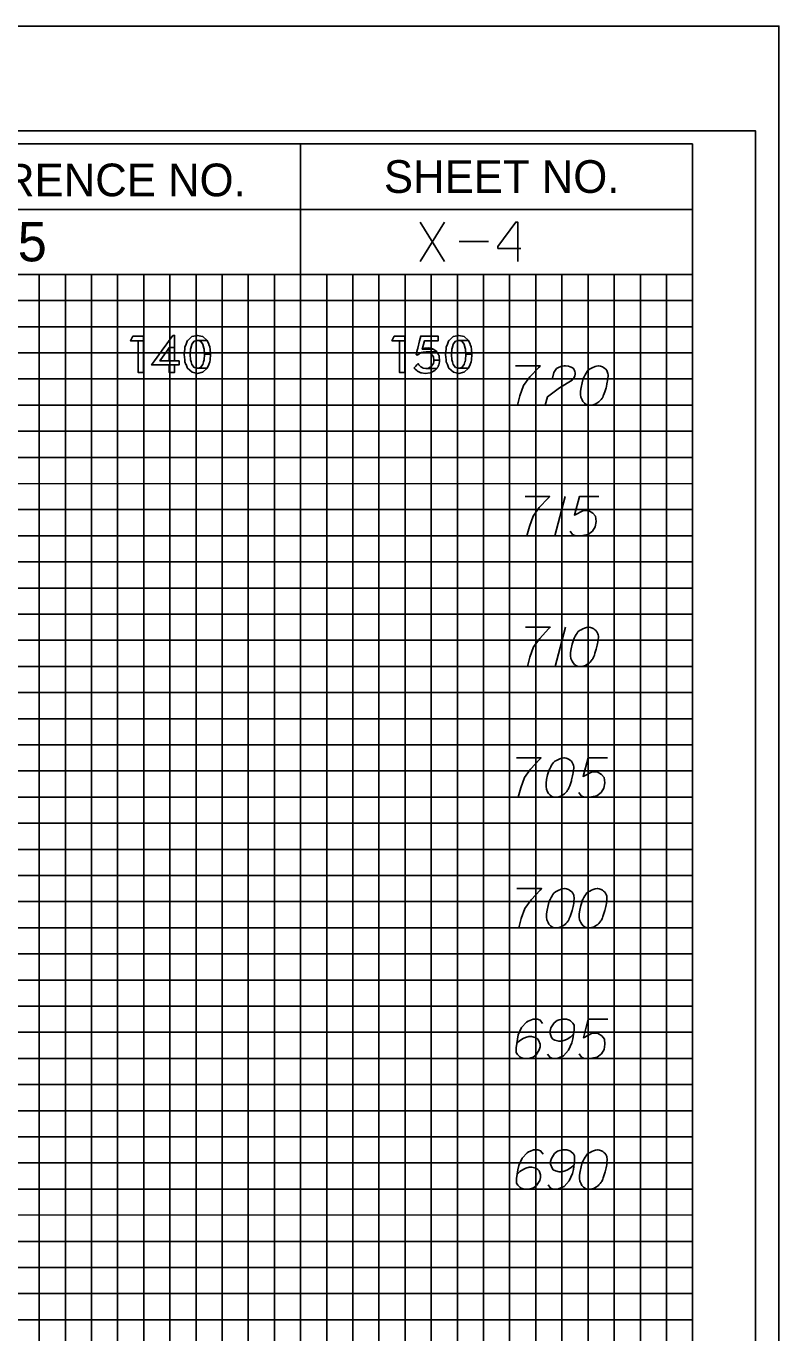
# Model space of a CAD drawing. Extents: x -13 to 323, y -5 to 1431.
# Drawn here: x 294.5 to 323.3, y 604.5 to 654.5 of the extents above; entities that cross this region are included whole.
import ezdxf

# ---------------------------------------------------------------- set-up
doc = ezdxf.new("R2010")
doc.units = 0
for name, color, linetype in [('Prop XS Elevation Labels', 7, 'Continuous'), ('Prop XS Offset Labels', 7, 'Continuous'), ('Prop XS Project Number', 7, 'Continuous'), ('Prop XS Sheet Number', 7, 'Continuous'), ('Sheet Cross Section CELL', 7, 'Continuous'), ('Sheet Cross Section Grid Major CELL', 7, 'Continuous'), ('Sheet Cross Section Grid Middle CELL', 7, 'Continuous'), ('Sheet Cross Section Grid Minor 1 CELL', 7, 'Continuous'), ('Sheet Cross Section Grid Minor 2 CELL', 7, 'Continuous'), ('Sheet Cutting Line CELL', 7, 'Continuous'), ('Sheet DOT Grid CELL', 7, 'Continuous'), ('Sheet Plot Border Inside CELL', 7, 'Continuous'), ('Sheet Plot Border Outside CELL', 7, 'Continuous')]:
    doc.layers.add(name, color=color, linetype=linetype)

msp = doc.modelspace()

# ---------------------------------------------------------------- linework, layer by layer
at = {"layer": 'Prop XS Elevation Labels'}
for p, q in [((315.124, 636.5), (314.723, 635)), ((315.142, 631.5), (314.74, 630))]:
    msp.add_line(p, q, dxfattribs=at)
for points in [[(313.228, 641.5), (314.173, 641.5), (314.114, 641.441), (313.772, 641.075), (313.535, 640.744), (313.394, 640.354), (313.299, 640)], [(314.634, 641.028), (314.693, 641.252), (314.787, 641.394), (314.894, 641.453), (315, 641.488), (315.083, 641.5), (315.142, 641.5), (315.248, 641.488), (315.319, 641.465), (315.354, 641.453), (315.425, 641.417), (315.461, 641.37), (315.484, 641.323), (315.496, 641.287), (315.508, 641.24), (315.508, 641.181), (315.496, 641.122), (315.484, 641.087), (315.461, 641.039), (315.425, 640.992), (315.39, 640.957), (314.906, 640.661), (314.445, 640.319), (314.362, 640), (315.437, 640)], [(316.417, 641.5), (316.394, 641.5), (316.323, 641.488), (316.276, 641.476), (316.24, 641.465), (316.181, 641.441), (316.11, 641.406), (316.051, 641.37), (315.992, 641.323), (315.957, 641.276), (315.921, 641.217), (315.886, 641.158), (315.85, 641.087), (315.827, 641.039), (315.803, 640.969), (315.768, 640.85), (315.732, 640.673), (315.709, 640.531), (315.709, 640.402), (315.721, 640.307), (315.768, 640.201), (315.803, 640.142), (315.862, 640.071), (315.933, 640.024), (315.968, 640.012), (316.039, 640), (316.098, 640), (316.193, 640.012), (316.276, 640.035), (316.335, 640.071), (316.417, 640.13), (316.453, 640.165), (316.5, 640.213), (316.535, 640.26), (316.559, 640.295), (316.583, 640.354), (316.594, 640.378), (316.618, 640.437), (316.642, 640.508), (316.665, 640.579), (316.677, 640.626), (316.689, 640.661), (316.701, 640.709), (316.724, 640.815), (316.736, 640.874), (316.748, 640.933), (316.76, 641.016), (316.772, 641.122), (316.772, 641.158), (316.76, 641.205), (316.748, 641.252), (316.713, 641.323), (316.677, 641.37), (316.642, 641.406), (316.594, 641.441), (316.547, 641.465), (316.512, 641.476), (316.476, 641.488), (316.417, 641.5)], [(313.589, 636.5), (314.533, 636.5), (314.474, 636.441), (314.132, 636.075), (313.896, 635.744), (313.754, 635.354), (313.659, 635)], [(316.411, 636.5), (315.667, 636.5), (315.478, 635.791), (315.821, 635.969), (316.022, 635.969), (316.187, 635.862), (316.282, 635.744), (316.305, 635.543), (316.27, 635.342), (316.175, 635.177), (316.01, 635.047), (315.726, 635), (315.514, 635), (315.408, 635.047), (315.313, 635.177)], [(313.606, 631.5), (314.551, 631.5), (314.492, 631.441), (314.149, 631.075), (313.913, 630.744), (313.772, 630.354), (313.677, 630)], [(316.039, 631.5), (316.016, 631.5), (315.945, 631.488), (315.898, 631.476), (315.862, 631.465), (315.803, 631.441), (315.732, 631.406), (315.673, 631.37), (315.614, 631.323), (315.579, 631.276), (315.543, 631.217), (315.508, 631.158), (315.472, 631.087), (315.449, 631.039), (315.425, 630.969), (315.39, 630.85), (315.354, 630.673), (315.331, 630.531), (315.331, 630.402), (315.343, 630.307), (315.39, 630.201), (315.425, 630.142), (315.484, 630.071), (315.555, 630.024), (315.591, 630.012), (315.661, 630), (315.72, 630), (315.815, 630.012), (315.898, 630.035), (315.957, 630.071), (316.039, 630.13), (316.075, 630.165), (316.122, 630.213), (316.157, 630.26), (316.181, 630.295), (316.205, 630.354), (316.217, 630.378), (316.24, 630.437), (316.264, 630.508), (316.287, 630.579), (316.299, 630.626), (316.311, 630.661), (316.323, 630.709), (316.347, 630.815), (316.358, 630.874), (316.37, 630.933), (316.382, 631.016), (316.394, 631.122), (316.394, 631.158), (316.382, 631.205), (316.37, 631.252), (316.335, 631.323), (316.299, 631.37), (316.264, 631.406), (316.217, 631.441), (316.169, 631.465), (316.134, 631.476), (316.098, 631.488), (316.039, 631.5)], [(313.258, 626.5), (314.203, 626.5), (314.144, 626.441), (313.801, 626.075), (313.565, 625.744), (313.423, 625.354), (313.329, 625)], [(315.1, 626.5), (315.077, 626.5), (315.006, 626.488), (314.959, 626.476), (314.923, 626.465), (314.864, 626.441), (314.793, 626.406), (314.734, 626.37), (314.675, 626.323), (314.64, 626.276), (314.604, 626.217), (314.569, 626.158), (314.534, 626.087), (314.51, 626.039), (314.486, 625.969), (314.451, 625.85), (314.415, 625.673), (314.392, 625.531), (314.392, 625.402), (314.404, 625.307), (314.451, 625.201), (314.486, 625.142), (314.545, 625.071), (314.616, 625.024), (314.652, 625.012), (314.723, 625), (314.781, 625), (314.876, 625.012), (314.959, 625.035), (315.018, 625.071), (315.1, 625.13), (315.136, 625.165), (315.183, 625.213), (315.219, 625.26), (315.242, 625.295), (315.266, 625.354), (315.278, 625.378), (315.301, 625.437), (315.325, 625.508), (315.349, 625.579), (315.36, 625.626), (315.372, 625.661), (315.384, 625.709), (315.408, 625.815), (315.419, 625.874), (315.431, 625.933), (315.443, 626.016), (315.455, 626.122), (315.455, 626.158), (315.443, 626.205), (315.431, 626.252), (315.396, 626.323), (315.36, 626.37), (315.325, 626.406), (315.278, 626.441), (315.23, 626.465), (315.195, 626.476), (315.16, 626.488), (315.1, 626.5)], [(316.742, 626.5), (315.998, 626.5), (315.809, 625.791), (316.152, 625.969), (316.352, 625.969), (316.518, 625.862), (316.612, 625.744), (316.636, 625.543), (316.6, 625.342), (316.506, 625.177), (316.341, 625.047), (316.057, 625), (315.845, 625), (315.738, 625.047), (315.644, 625.177)], [(313.276, 621.5), (314.22, 621.5), (314.161, 621.441), (313.819, 621.075), (313.583, 620.744), (313.441, 620.354), (313.346, 620)], [(315.118, 621.5), (315.094, 621.5), (315.024, 621.488), (314.977, 621.476), (314.941, 621.465), (314.882, 621.441), (314.811, 621.406), (314.752, 621.37), (314.693, 621.323), (314.658, 621.276), (314.622, 621.217), (314.587, 621.158), (314.551, 621.087), (314.528, 621.039), (314.504, 620.969), (314.469, 620.85), (314.433, 620.673), (314.409, 620.531), (314.409, 620.402), (314.421, 620.307), (314.469, 620.201), (314.504, 620.142), (314.563, 620.071), (314.634, 620.024), (314.669, 620.012), (314.74, 620), (314.799, 620), (314.894, 620.012), (314.977, 620.035), (315.036, 620.071), (315.118, 620.13), (315.154, 620.165), (315.201, 620.213), (315.236, 620.26), (315.26, 620.295), (315.283, 620.354), (315.295, 620.378), (315.319, 620.437), (315.342, 620.508), (315.366, 620.579), (315.378, 620.626), (315.39, 620.661), (315.402, 620.709), (315.425, 620.815), (315.437, 620.874), (315.449, 620.933), (315.461, 621.016), (315.473, 621.122), (315.473, 621.158), (315.461, 621.205), (315.449, 621.252), (315.413, 621.323), (315.378, 621.37), (315.342, 621.406), (315.295, 621.441), (315.248, 621.465), (315.213, 621.476), (315.177, 621.488), (315.118, 621.5)], [(316.37, 621.5), (316.346, 621.5), (316.276, 621.488), (316.228, 621.476), (316.193, 621.465), (316.134, 621.441), (316.063, 621.406), (316.004, 621.37), (315.945, 621.323), (315.909, 621.276), (315.874, 621.217), (315.838, 621.158), (315.803, 621.087), (315.779, 621.039), (315.756, 620.969), (315.721, 620.85), (315.685, 620.673), (315.661, 620.531), (315.661, 620.402), (315.673, 620.307), (315.721, 620.201), (315.756, 620.142), (315.815, 620.071), (315.886, 620.024), (315.921, 620.012), (315.992, 620), (316.051, 620), (316.146, 620.012), (316.228, 620.035), (316.287, 620.071), (316.37, 620.13), (316.406, 620.165), (316.453, 620.213), (316.488, 620.26), (316.512, 620.295), (316.535, 620.354), (316.547, 620.378), (316.571, 620.437), (316.594, 620.508), (316.618, 620.579), (316.63, 620.626), (316.642, 620.661), (316.653, 620.709), (316.677, 620.815), (316.689, 620.874), (316.701, 620.933), (316.713, 621.016), (316.724, 621.122), (316.724, 621.158), (316.713, 621.205), (316.701, 621.252), (316.665, 621.323), (316.63, 621.37), (316.594, 621.406), (316.547, 621.441), (316.5, 621.465), (316.464, 621.476), (316.429, 621.488), (316.37, 621.5)], [(314.262, 616.335), (314.168, 616.465), (314.061, 616.5), (313.896, 616.5), (313.778, 616.453), (313.707, 616.429), (313.648, 616.394), (313.459, 616.181), (313.329, 615.898), (313.294, 615.744), (313.246, 615.402), (313.246, 615.224), (313.294, 615.154), (313.388, 615.059), (313.423, 615.035), (313.542, 615), (313.695, 615), (313.813, 615.024), (313.896, 615.047), (314.014, 615.142), (314.132, 615.331), (314.168, 615.449), (314.168, 615.543), (314.109, 615.697), (314.061, 615.756), (313.979, 615.803), (313.837, 615.839), (313.73, 615.839), (313.601, 615.803), (313.518, 615.768), (313.376, 615.673), (313.305, 615.614), (313.27, 615.579)], [(314.451, 615.165), (314.545, 615.035), (314.652, 615), (314.817, 615), (314.935, 615.047), (315.006, 615.071), (315.065, 615.106), (315.254, 615.319), (315.384, 615.602), (315.419, 615.756), (315.467, 616.098), (315.467, 616.276), (315.419, 616.346), (315.325, 616.441), (315.289, 616.465), (315.171, 616.5), (315.018, 616.5), (314.9, 616.476), (314.817, 616.453), (314.699, 616.358), (314.581, 616.169), (314.545, 616.051), (314.545, 615.957), (314.604, 615.803), (314.652, 615.744), (314.734, 615.697), (314.876, 615.661), (314.982, 615.661), (315.112, 615.697), (315.195, 615.732), (315.337, 615.827), (315.408, 615.886), (315.443, 615.921)], [(316.754, 616.5), (316.01, 616.5), (315.821, 615.791), (316.163, 615.969), (316.364, 615.969), (316.529, 615.862), (316.624, 615.744), (316.647, 615.543), (316.612, 615.342), (316.517, 615.177), (316.352, 615.047), (316.069, 615), (315.856, 615), (315.75, 615.047), (315.655, 615.177)], [(314.28, 611.335), (314.185, 611.465), (314.079, 611.5), (313.914, 611.5), (313.795, 611.453), (313.725, 611.429), (313.666, 611.394), (313.477, 611.181), (313.347, 610.898), (313.311, 610.744), (313.264, 610.402), (313.264, 610.224), (313.311, 610.154), (313.406, 610.059), (313.441, 610.035), (313.559, 610), (313.713, 610), (313.831, 610.024), (313.914, 610.047), (314.032, 610.142), (314.15, 610.331), (314.185, 610.449), (314.185, 610.543), (314.126, 610.697), (314.079, 610.756), (313.996, 610.803), (313.854, 610.839), (313.748, 610.839), (313.618, 610.803), (313.536, 610.768), (313.394, 610.673), (313.323, 610.614), (313.288, 610.579)], [(314.468, 610.165), (314.563, 610.035), (314.669, 610), (314.835, 610), (314.953, 610.047), (315.024, 610.071), (315.083, 610.106), (315.272, 610.319), (315.401, 610.602), (315.437, 610.756), (315.484, 611.098), (315.484, 611.276), (315.437, 611.346), (315.342, 611.441), (315.307, 611.465), (315.189, 611.5), (315.036, 611.5), (314.917, 611.476), (314.835, 611.453), (314.717, 611.358), (314.598, 611.169), (314.563, 611.051), (314.563, 610.957), (314.622, 610.803), (314.669, 610.744), (314.752, 610.697), (314.894, 610.661), (315, 610.661), (315.13, 610.697), (315.213, 610.732), (315.354, 610.827), (315.425, 610.886), (315.461, 610.921)], [(316.382, 611.5), (316.358, 611.5), (316.287, 611.488), (316.24, 611.476), (316.204, 611.465), (316.145, 611.441), (316.074, 611.406), (316.015, 611.37), (315.956, 611.323), (315.921, 611.276), (315.885, 611.217), (315.85, 611.158), (315.815, 611.087), (315.791, 611.039), (315.767, 610.969), (315.732, 610.85), (315.697, 610.673), (315.673, 610.531), (315.673, 610.402), (315.685, 610.307), (315.732, 610.201), (315.767, 610.142), (315.827, 610.071), (315.897, 610.024), (315.933, 610.012), (316.004, 610), (316.063, 610), (316.157, 610.012), (316.24, 610.035), (316.299, 610.071), (316.382, 610.13), (316.417, 610.165), (316.464, 610.213), (316.5, 610.26), (316.523, 610.295), (316.547, 610.354), (316.559, 610.378), (316.582, 610.437), (316.606, 610.508), (316.63, 610.579), (316.642, 610.626), (316.653, 610.661), (316.665, 610.709), (316.689, 610.815), (316.701, 610.874), (316.712, 610.933), (316.724, 611.016), (316.736, 611.122), (316.736, 611.158), (316.724, 611.205), (316.712, 611.252), (316.677, 611.323), (316.642, 611.37), (316.606, 611.406), (316.559, 611.441), (316.512, 611.465), (316.476, 611.476), (316.441, 611.488), (316.382, 611.5)]]:
    msp.add_lwpolyline(points, dxfattribs=at)
at = {"layer": 'Prop XS Offset Labels'}
for points in [[(298.581, 642.641), (298.492, 642.459), (298.99, 642.459), (298.99, 642.641)], [(299.411, 641.693), (299.297, 641.534), (300.35, 641.534), (300.35, 641.693), (299.618, 641.693), (299.878, 642.059), (299.935, 642.139), (299.977, 642.199), (300.179, 642.199), (300.179, 642.668), (300.114, 642.668), (299.775, 642.199), (299.733, 642.139), (299.675, 642.059)], [(300.851, 641.255), (301.051, 641.214), (301.245, 641.255), (301.256, 641.257), (301.422, 641.409), (301.048, 641.409), (301.038, 641.411), (301.033, 641.413), (300.928, 641.442), (300.841, 641.555), (300.841, 641.556), (300.841, 641.556), (300.813, 641.657), (300.813, 641.659), (300.793, 641.732), (300.792, 641.736), (300.774, 641.939), (300.774, 641.941), (300.774, 641.943), (300.792, 642.145), (300.812, 642.222), (300.813, 642.224), (300.839, 642.322), (300.84, 642.325), (300.928, 642.44), (301.041, 642.469), (301.045, 642.47), (301.055, 642.473), (301.425, 642.473), (301.262, 642.622), (301.254, 642.624), (301.053, 642.668), (301.053, 642.668), (300.845, 642.624), (300.843, 642.622), (300.681, 642.473), (300.678, 642.47), (300.678, 642.469), (300.665, 642.44), (300.618, 642.325), (300.617, 642.322), (300.577, 642.224), (300.576, 642.222), (300.568, 642.145), (300.547, 641.943), (300.547, 641.941), (300.547, 641.939), (300.567, 641.736), (300.567, 641.732), (300.575, 641.659), (300.575, 641.657), (300.616, 641.556), (300.617, 641.555), (300.663, 641.442), (300.675, 641.413), (300.676, 641.411), (300.679, 641.409), (300.848, 641.257)], [(308.581, 642.641), (308.492, 642.459), (308.99, 642.459), (308.99, 642.641)], [(309.427, 641.94), (309.424, 641.928), (309.495, 641.928), (309.508, 641.94), (309.524, 641.954), (309.595, 641.997), (309.627, 642.007), (309.697, 642.029), (309.811, 642.035), (310.219, 642.035), (310.211, 642.05), (310.076, 642.145), (309.655, 642.145), (309.658, 642.158), (309.658, 642.158), (309.663, 642.178), (309.738, 642.456), (310.263, 642.456), (310.263, 642.641), (309.6, 642.641), (309.554, 642.456), (309.486, 642.178), (309.481, 642.158), (309.478, 642.145), (309.454, 642.05), (309.451, 642.035), (309.449, 642.029), (309.444, 642.007), (309.441, 641.997), (309.431, 641.954)], [(310.851, 641.255), (311.051, 641.214), (311.245, 641.255), (311.256, 641.257), (311.422, 641.409), (311.048, 641.409), (311.038, 641.411), (311.033, 641.413), (310.928, 641.442), (310.841, 641.555), (310.841, 641.556), (310.841, 641.556), (310.813, 641.657), (310.813, 641.659), (310.793, 641.732), (310.792, 641.736), (310.774, 641.939), (310.774, 641.941), (310.774, 641.943), (310.792, 642.145), (310.812, 642.222), (310.813, 642.224), (310.839, 642.322), (310.84, 642.325), (310.928, 642.44), (311.041, 642.469), (311.045, 642.47), (311.055, 642.473), (311.425, 642.473), (311.262, 642.622), (311.254, 642.624), (311.053, 642.668), (311.053, 642.668), (310.845, 642.624), (310.843, 642.622), (310.681, 642.473), (310.678, 642.47), (310.678, 642.469), (310.665, 642.44), (310.618, 642.325), (310.617, 642.322), (310.577, 642.224), (310.576, 642.222), (310.568, 642.145), (310.547, 641.943), (310.547, 641.941), (310.547, 641.939), (310.567, 641.736), (310.567, 641.732), (310.575, 641.659), (310.575, 641.657), (310.616, 641.556), (310.617, 641.555), (310.663, 641.442), (310.675, 641.413), (310.676, 641.411), (310.679, 641.409), (310.848, 641.257)], [(298.781, 642.459), (298.781, 641.25), (298.99, 641.25), (298.99, 642.459)], [(299.97, 642.059), (299.97, 641.693), (300.179, 641.693), (300.179, 642.059), (300.179, 642.139), (300.179, 642.199), (299.977, 642.199), (299.973, 642.139)], [(301.312, 642.145), (301.328, 641.943), (301.555, 641.943), (301.536, 642.145), (301.528, 642.222), (301.528, 642.224), (301.527, 642.224), (301.488, 642.322), (301.488, 642.322), (301.487, 642.325), (301.441, 642.44), (301.44, 642.44), (301.429, 642.469), (301.428, 642.47), (301.425, 642.473), (301.055, 642.473), (301.065, 642.47), (301.068, 642.469), (301.175, 642.44), (301.262, 642.325), (301.265, 642.322), (301.291, 642.224), (301.291, 642.222)], [(308.781, 642.459), (308.781, 641.25), (308.99, 641.25), (308.99, 642.459)], [(309.692, 642.158), (309.655, 642.145), (310.076, 642.145), (310.058, 642.158), (309.961, 642.178), (309.75, 642.178)], [(309.888, 642.192), (309.75, 642.178), (309.96, 642.178), (309.888, 642.192)], [(310.083, 641.841), (310.105, 641.721), (310.318, 641.721), (310.307, 641.841), (310.307, 641.841), (310.303, 641.881), (310.284, 641.916), (310.278, 641.928), (310.271, 641.94), (310.263, 641.954), (310.24, 641.997), (310.235, 642.007), (310.223, 642.029), (310.219, 642.035), (309.811, 642.035), (309.838, 642.029), (309.928, 642.007), (309.942, 641.997), (310.003, 641.954), (310.024, 641.94), (310.031, 641.928), (310.038, 641.916), (310.059, 641.881)], [(311.312, 642.145), (311.328, 641.943), (311.555, 641.943), (311.536, 642.145), (311.528, 642.222), (311.528, 642.224), (311.527, 642.224), (311.488, 642.322), (311.488, 642.322), (311.487, 642.325), (311.441, 642.44), (311.44, 642.44), (311.429, 642.469), (311.428, 642.47), (311.425, 642.473), (311.055, 642.473), (311.065, 642.47), (311.068, 642.469), (311.175, 642.44), (311.262, 642.325), (311.265, 642.322), (311.291, 642.224), (311.291, 642.222)], [(299.97, 641.534), (299.97, 641.25), (300.179, 641.25), (300.179, 641.534)], [(301.058, 641.411), (301.048, 641.409), (301.422, 641.409), (301.425, 641.411), (301.426, 641.413), (301.438, 641.442), (301.485, 641.555), (301.485, 641.556), (301.527, 641.657), (301.528, 641.659), (301.535, 641.732), (301.535, 641.736), (301.555, 641.939), (301.556, 641.941), (301.555, 641.943), (301.328, 641.943), (301.328, 641.941), (301.328, 641.939), (301.312, 641.736), (301.312, 641.732), (301.292, 641.659), (301.291, 641.657), (301.264, 641.556), (301.263, 641.555), (301.175, 641.442), (301.063, 641.413)], [(309.626, 641.233), (309.762, 641.214), (309.959, 641.233), (309.968, 641.237), (310.091, 641.297), (310.091, 641.297), (310.141, 641.321), (310.185, 641.375), (310.204, 641.399), (309.793, 641.399), (309.683, 641.418), (309.682, 641.419), (309.679, 641.42), (309.596, 641.466), (309.586, 641.477), (309.58, 641.483), (309.58, 641.483), (309.529, 641.535), (309.497, 641.585), (309.497, 641.585), (309.451, 641.535), (309.404, 641.483), (309.399, 641.477), (309.39, 641.466), (309.348, 641.42), (309.347, 641.419), (309.348, 641.418), (309.363, 641.399), (309.382, 641.375), (309.445, 641.321), (309.474, 641.297), (309.598, 641.237)], [(309.424, 641.928), (309.482, 641.916), (309.495, 641.928)], [(309.9, 641.418), (309.793, 641.399), (310.204, 641.399), (310.22, 641.418), (310.221, 641.419), (310.222, 641.42), (310.222, 641.42), (310.259, 641.466), (310.268, 641.477), (310.27, 641.483), (310.284, 641.535), (310.299, 641.59), (310.322, 641.674), (310.318, 641.721), (310.105, 641.721), (310.097, 641.674), (310.082, 641.59), (310.047, 641.535), (310.014, 641.483), (310.004, 641.477), (309.987, 641.466), (309.913, 641.42), (309.905, 641.419)], [(311.058, 641.411), (311.048, 641.409), (311.422, 641.409), (311.425, 641.411), (311.426, 641.413), (311.438, 641.442), (311.485, 641.555), (311.485, 641.556), (311.527, 641.657), (311.528, 641.659), (311.535, 641.732), (311.535, 641.736), (311.555, 641.939), (311.556, 641.941), (311.555, 641.943), (311.328, 641.943), (311.328, 641.941), (311.328, 641.939), (311.312, 641.736), (311.312, 641.732), (311.292, 641.659), (311.291, 641.657), (311.264, 641.556), (311.263, 641.555), (311.175, 641.442), (311.063, 641.413)]]:
    msp.add_lwpolyline(points, close=True, dxfattribs=at)
at = {"layer": 'Prop XS Sheet Number'}
for p, q in [((309.575, 647), (310.508, 645.5)), ((310.508, 647), (309.575, 645.5)), ((311.063, 646.256), (312.185, 646.256))]:
    msp.add_line(p, q, dxfattribs=at)
msp.add_lwpolyline([(313.425, 645.996), (312.551, 645.996), (312.551, 646.067), (313.236, 647), (313.307, 647), (313.307, 645.5)], dxfattribs=at)
at = {"layer": 'Sheet Cross Section CELL'}
for p, q in [((305, 650), (305, 645)), ((305, 645), (305, 650)), ((320, 647.49), (280, 647.49)), ((280, 645), (320, 645))]:
    msp.add_line(p, q, dxfattribs=at)
for points in [[(320, 650), (0, 650), (0, 440), (320, 440)], [(320, 650), (280, 650), (280, 645), (320, 645)]]:
    msp.add_lwpolyline(points, close=True, dxfattribs=at)
at = {"layer": 'Sheet Cross Section Grid Major CELL'}
for p, q in [((310, 645), (300, 645)), ((300, 645), (300, 440)), ((310, 440), (310, 645))]:
    msp.add_line(p, q, dxfattribs=at)
for points in [[(0, 640), (320, 640), (320, 630), (0, 630)], [(0, 620), (320, 620), (320, 610), (0, 610)]]:
    msp.add_lwpolyline(points, dxfattribs=at)
at = {"layer": 'Sheet Cross Section Grid Middle CELL'}
for points in [[(295, 440), (295, 645), (305, 645), (305, 440)], [(315, 440), (315, 645)], [(0, 625), (320, 625), (320, 635), (0, 635)], [(0, 605), (320, 605), (320, 615), (0, 615)]]:
    msp.add_lwpolyline(points, dxfattribs=at)
at = {"layer": 'Sheet Cross Section Grid Minor 1 CELL'}
msp.add_line((0, 644), (320, 644), dxfattribs=at)
for points in [[(0, 643), (270, 643), (320, 643), (320, 642), (0, 642)], [(0, 641), (320, 641), (320, 639), (0, 639)], [(0, 638), (320, 638), (320, 637), (0, 636.98)], [(0, 636), (320, 636), (320, 634), (0, 634)], [(0, 633), (320, 633), (320, 632), (0, 632)], [(0, 631), (320, 631), (320, 629), (0, 629)], [(0, 628), (320, 628), (320, 627), (0, 627)], [(0, 626), (320, 626), (320, 624), (0, 624)], [(0, 623), (320, 623), (320, 622), (0, 622)], [(0, 621), (320, 621), (320, 619), (0, 619)], [(0, 618), (320, 618), (320, 617), (0, 617)], [(0, 616), (320, 616), (320, 613.95), (320, 613), (320, 612), (0, 612)], [(0, 614), (320, 614), (320, 613), (0, 613)], [(0, 611), (320, 611), (320, 609), (0, 609.03)], [(0, 609.03), (320, 609), (320, 608), (0, 608)], [(0, 607), (320, 607), (320, 606), (0, 606)]]:
    msp.add_lwpolyline(points, dxfattribs=at)
at = {"layer": 'Sheet Cross Section Grid Minor 2 CELL'}
for points in [[(295, 440), (296, 440), (296, 645), (297, 645), (297, 440)], [(297, 440), (298, 440), (298, 645), (299, 645), (299, 440)], [(300, 440), (301, 440), (301, 645), (302, 645), (302, 440)], [(302, 440), (303, 440), (303, 645), (304, 645), (304, 440)], [(305, 440), (306, 440), (306, 645), (307, 645), (307, 440)], [(307, 440), (308, 440), (308, 645), (309, 645), (309, 440)], [(310, 440), (311, 440), (311, 645), (312, 645), (312, 440)], [(312, 440), (313, 440), (313, 645), (314, 645), (314, 440)], [(315, 440), (316, 440), (316, 645), (317, 645), (317, 440)], [(317, 440), (318, 440), (318, 645), (319, 645), (319, 440)]]:
    msp.add_lwpolyline(points, dxfattribs=at)
at = {"layer": 'Sheet Cutting Line CELL'}
msp.add_line((323.3, 654.5), (-13.4, 654.5), dxfattribs=at)
at = {"layer": 'Sheet DOT Grid CELL'}
for p, q in [((300, 440), (300, 644.687)), ((310, 440), (310, 644.687)), ((0, 640), (320, 640)), ((0, 630), (320, 630)), ((0, 620), (320, 620)), ((0, 610), (320, 610))]:
    msp.add_line(p, q, dxfattribs=at)
at = {"layer": 'Sheet Plot Border Inside CELL'}
msp.add_lwpolyline([(-10.8, 439.5), (322.4, 439.5), (322.4, 650.5), (-10.8, 650.5)], close=True, dxfattribs=at)
at = {"layer": 'Sheet Plot Border Outside CELL'}
msp.add_lwpolyline([(-13.4, 435.5), (323.3, 435.5), (323.3, 654.5), (-13.4, 654.5)], close=True, dxfattribs=at)

# ---------------------------------------------------------------- texts
at = {"layer": 'Prop XS Project Number'}
msp.add_text('HL-0025', height=1.5, dxfattribs=at).set_placement((287.598, 645.5))
at = {"layer": 'Sheet Cross Section CELL'}
for s, height, p in [('PROJ. REFERENCE NO.', 1.24998, (283.77, 647.99)), ('SHEET NO.', 1.25, (308.19, 648.12))]:
    msp.add_text(s, height=height, dxfattribs=at).set_placement(p)

doc.saveas('drawing.dxf')
